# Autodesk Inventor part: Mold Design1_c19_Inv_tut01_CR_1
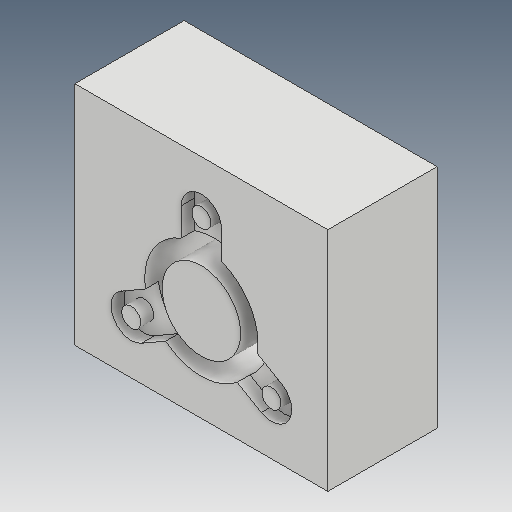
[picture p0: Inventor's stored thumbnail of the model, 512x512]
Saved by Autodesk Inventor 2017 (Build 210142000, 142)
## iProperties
Created: 2016-07
Part Number: Mold Design1_c19_Inv_tut01_CR_1
Material: Generic
Document SubType Name: Modeling
Designer: Sandeep
Density: 1 g/cm^3
Appearance: Default
Author: Sandeep
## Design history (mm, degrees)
node "Mold Design1_c19_Inv_tut01_CR_Base"
feature "Solid1::Mold Design1_c19_Inv_tut01_CR_Base"
tag "TaggingFeature1"
body "Solid1"
feature "Mold Design1_c19_Inv_tut01_CR_Base_Bodies"
